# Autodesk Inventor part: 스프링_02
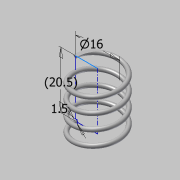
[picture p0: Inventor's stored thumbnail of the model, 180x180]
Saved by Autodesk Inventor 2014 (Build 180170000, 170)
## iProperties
Created: 2015-07
Part Number: 스프링_02
Material: 강철, 연강
Document SubType Name: Modeling
Designer: Administrator
Density: 7.86 g/cm^3
Appearance: 강철
Mass: 2.74935 g
Surface Area: 9.46884 cm^2
Volume: 0.34979 cm^3
Author: Administrator
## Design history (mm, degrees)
sketch "스케치1"
  geometry: L1 (0, 0)-(8, 0); L2 (8, 0)-(8, 20.5); L3 (8, 20.5)-(0, 20.5); L4 (0, 20.5)-(0, 0); C1 r 0.75 at (8, 0)
  constraints: 8 end point, 2 parallel, 1 centre point, 1 coincident, 1 horizontal, 1 perpendicular
  dimensions: "d0" = 20.5 distance between parallel lines of L1 L3 (derived); "d1" = 16 diameter of L2 L4; "d2" = 1.5 diameter of C1
feature "코일1" pitch "d3" = 10; turns "d5" = 4; dims "d4" = 20.5 (= d0), "d6" = 0, angle "d7" = 90 deg, angle "d8" = 90 deg, "d9" = 0, "d10" = 0
node "작업 평면1"
sketch "스케치2"
  geometry: L1 (-0.75, 0)-(0.75, 0) reference; 1 further point
  constraints: 1 horizontal alignment
extrude "돌출1" cut sketch "스케치2" stored distance "d12" = 10; taper "d13" = 0 deg
node "작업 평면2"
sketch "스케치3"
  geometry: L1 (7.25, 0)-(8.75, 0) reference; 1 further point
  constraints: 1 horizontal alignment
extrude "돌출2" cut sketch "스케치3" stored distance "d15" = 10; taper "d16" = 0 deg
node "솔리드1"
node "절단 모서리 투영1"
node "절단 모서리 투영2"
other parameters: "d11" = 90 deg, "d14" = 90 deg
